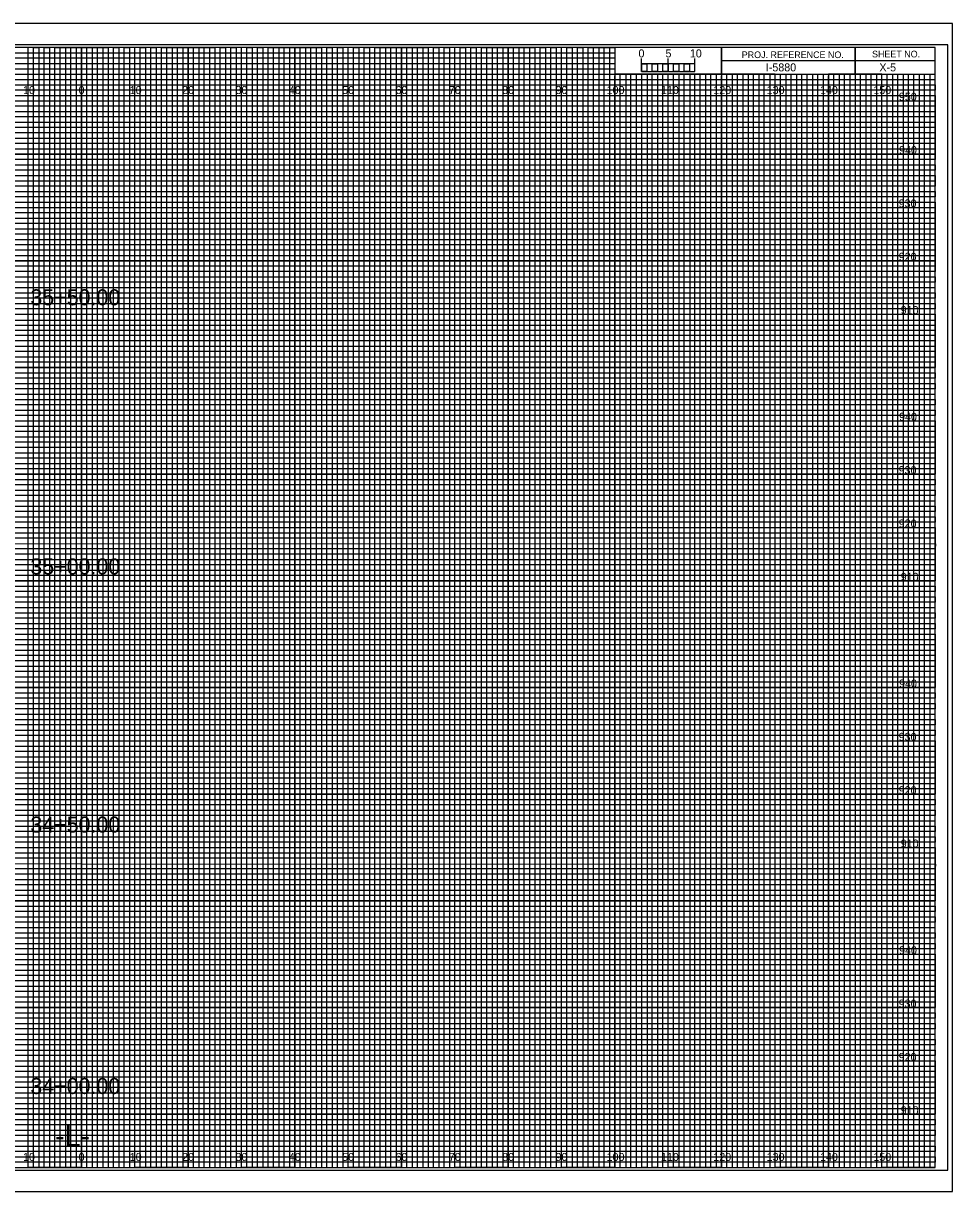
# Model space of a CAD drawing. Extents: x -13 to 323, y -4 to 3074.
# Drawn here: x 149.1 to 323.3, y 655.5 to 874.5 of the extents above; entities that cross this region are included whole.
import ezdxf

# ---------------------------------------------------------------- set-up
doc = ezdxf.new("R2010")
doc.units = 0
for name, color, linetype in [('Prop XS Alignment Label', 7, 'Continuous'), ('Prop XS Bar Scale Labels', 7, 'Continuous'), ('Prop XS Elevation Labels', 7, 'Continuous'), ('Prop XS Offset Labels', 7, 'Continuous'), ('Prop XS Project Number', 7, 'Continuous'), ('Prop XS Sheet Number', 7, 'Continuous'), ('Prop XS Station Labels', 7, 'Continuous'), ('Sheet Cross Section CELL', 7, 'Continuous'), ('Sheet Cross Section Grid Major CELL', 7, 'Continuous'), ('Sheet Cross Section Grid Middle CELL', 7, 'Continuous'), ('Sheet Cross Section Grid Minor 1 CELL', 7, 'Continuous'), ('Sheet Cross Section Grid Minor 2 CELL', 7, 'Continuous'), ('Sheet Cross Section Scale CELL', 7, 'Continuous'), ('Sheet Cutting Line CELL', 7, 'Continuous'), ('Sheet DOT Grid CELL', 7, 'Continuous'), ('Sheet Plot Border Inside CELL', 7, 'Continuous'), ('Sheet Plot Border Outside CELL', 7, 'Continuous')]:
    doc.layers.add(name, color=color, linetype=linetype)

msp = doc.modelspace()

# ---------------------------------------------------------------- linework, layer by layer
at = {"layer": 'Sheet Cross Section CELL'}
for p, q in [((305, 870), (305, 865)), ((305, 865), (305, 870)), ((280, 867.5), (280, 865)), ((320, 867.49), (280, 867.49)), ((280, 865), (320, 865))]:
    msp.add_line(p, q, dxfattribs=at)
for points in [[(320, 870), (0, 870), (0, 660), (320, 660)], [(280, 870), (260, 870), (260, 865.03), (280, 865.03)], [(320, 870), (280, 870), (280, 865), (320, 865)]]:
    msp.add_lwpolyline(points, close=True, dxfattribs=at)
at = {"layer": 'Sheet Cross Section Grid Major CELL'}
for p, q in [((150, 870), (140, 870)), ((150, 660), (150, 870)), ((170, 870), (160, 870)), ((160, 870), (160, 660)), ((170, 660), (170, 870)), ((190, 870), (180, 870)), ((180, 870), (180, 660)), ((190, 660), (190, 870)), ((210, 870), (200, 870)), ((200, 870), (200, 660)), ((210, 660), (210, 870)), ((230, 870), (220, 870)), ((220, 870), (220, 660)), ((230, 660), (230, 870)), ((250, 870), (240, 870)), ((240, 870), (240, 660)), ((250, 660), (250, 870)), ((260, 870), (260, 660)), ((270, 660), (270, 865)), ((290, 865), (280, 865)), ((280, 865), (280, 660)), ((290, 660), (290, 865)), ((310, 865), (300, 865)), ((300, 865), (300, 660)), ((310, 660), (310, 865)), ((160, 660), (150, 660)), ((180, 660), (170, 660)), ((200, 660), (190, 660)), ((220, 660), (210, 660)), ((240, 660), (230, 660)), ((260, 660), (250, 660)), ((280, 660), (270, 660)), ((300, 660), (290, 660)), ((320, 660), (310, 660)), ((320, 660), (320, 660))]:
    msp.add_line(p, q, dxfattribs=at)
for points in [[(0, 860), (320, 860), (320, 850), (0, 850)], [(0, 840), (320, 840), (320, 830), (0, 830)], [(0, 820), (320, 820), (320, 810), (0, 810)], [(0, 800), (320, 800), (320, 790), (0, 790)], [(0, 780), (320, 780), (320, 770), (0, 770)], [(0, 760), (320, 760), (320, 750), (0, 750)], [(0, 740), (320, 740), (320, 730), (0, 730)], [(0, 720), (320, 720), (320, 710), (0, 710)], [(0, 700), (320, 700), (320, 690), (0, 690)], [(0, 680), (320, 680), (320, 670), (0, 670)]]:
    msp.add_lwpolyline(points, dxfattribs=at)
at = {"layer": 'Sheet Cross Section Grid Middle CELL'}
for points in [[(145, 660), (155, 660), (155, 870), (165, 870), (165, 660), (175, 660), (175, 870), (185, 870), (185, 660), (195, 660), (195, 870), (205, 870), (205, 660), (215, 660), (215, 870), (225, 870), (225, 660), (235, 660), (235, 870), (245, 870), (245, 660), (255, 660), (255, 870), (259.93, 870), (260, 870), (260, 865), (264.99, 865), (264.99, 660), (275, 660), (275, 865), (285, 865), (285, 660), (295, 660), (295, 865), (305, 865), (305, 660), (315, 660), (315, 865)], [(0, 865), (275, 865)], [(0, 845), (320, 845), (320, 855), (0, 855)], [(0, 825), (320, 825), (320, 835), (0, 835)], [(0, 805), (320, 805), (320, 815), (0, 815)], [(0, 785), (320, 785), (320, 795), (0, 795)], [(0, 765), (320, 765), (320, 775), (0, 775)], [(0, 745), (320, 745), (320, 755), (0, 755)], [(0, 725), (320, 725), (320, 735), (0, 735)], [(0, 705), (320, 705), (320, 715), (0, 715)], [(0, 685), (320, 685), (320, 695), (0, 695)], [(0, 665), (320, 665), (320, 675), (0, 675)]]:
    msp.add_lwpolyline(points, dxfattribs=at)
at = {"layer": 'Sheet Cross Section Grid Minor 1 CELL'}
for p, q in [((0, 869), (260, 869)), ((260, 867.98), (0, 867.98)), ((260, 869), (260, 867.98)), ((0, 867), (260, 867)), ((260, 865.89), (0, 865.89)), ((260, 867), (260, 865.89)), ((0, 864), (320, 864))]:
    msp.add_line(p, q, dxfattribs=at)
for points in [[(0, 863), (270, 863), (320, 863), (320, 862), (0, 862)], [(0, 861), (320, 861), (320, 859), (0, 859)], [(0, 858), (320, 858), (320, 857), (0, 856.98)], [(0, 856), (320, 856), (320, 854), (0, 854)], [(0, 853), (320, 853), (320, 852), (0, 852)], [(0, 851), (320, 851), (320, 849), (0, 849)], [(0, 848), (320, 848), (320, 847), (0, 847)], [(0, 846), (320, 846), (320, 844), (0, 844)], [(0, 843), (320, 843), (320, 842), (0, 842)], [(0, 841), (320, 841), (320, 839), (0, 839)], [(0, 838), (320, 838), (320, 837), (0, 837)], [(0, 836), (320, 836), (320, 833.95), (320, 833), (320, 832), (0, 832)], [(0, 834), (320, 834), (320, 833), (0, 833)], [(0, 831), (320, 831), (320, 829), (0, 829.03)], [(0, 829.03), (320, 829), (320, 828), (0, 828)], [(0, 827), (320, 827), (320, 826), (0, 826)], [(0, 824), (320, 824), (320, 823), (0, 823)], [(0, 822), (320, 822), (320, 821), (0, 821)], [(-0.07, 818.89), (320, 818.89), (320, 817.88), (-0.07, 817.88)], [(0, 817), (320, 817), (320, 816), (0, 816)], [(0, 814), (320, 814), (320, 813), (0, 813)], [(0, 812), (320, 812), (320, 811), (0, 811)], [(0, 809), (320, 809), (320, 808), (0, 808)], [(0, 807), (320, 807), (320, 806), (0, 806)], [(0, 804), (320, 804), (320, 803), (0, 803)], [(0, 802), (320, 802), (320, 801), (0, 801)], [(0, 799), (320, 799), (319.99, 797.98), (0, 798)], [(0, 797), (320, 797), (320, 796), (0, 796)], [(0, 794), (320, 794), (320, 793), (0, 793)], [(0, 792), (320, 792), (320, 791), (0, 791)], [(0, 789), (320, 789), (320, 788), (0, 788)], [(0, 787), (320, 787), (320, 786), (0, 786)], [(0, 784), (320, 784), (320, 783), (0, 783)], [(0, 782), (320, 782), (320, 781), (0, 781)], [(0, 779), (320, 779), (320, 778), (0, 778)], [(0, 776.99), (320.07, 776.91), (320, 776), (0, 776)], [(0, 774), (320, 774), (320, 773), (0, 773)], [(0, 772), (320, 772), (320, 771), (0, 771)], [(0, 769), (320, 769), (320, 768), (0, 768)], [(0, 767), (320, 767), (320, 766), (0, 766)], [(0, 764), (320, 764), (320, 763), (0, 763)], [(0, 762), (320, 762), (320, 761), (0, 761)], [(0, 759), (320, 759), (320, 758), (0, 758)], [(0, 757), (320, 757), (320, 756), (0, 756)], [(0, 754), (320, 754), (320, 753), (0, 753)], [(0, 752), (320, 752), (320, 751), (0, 751)], [(0, 749), (320, 749), (320, 748), (0, 748)], [(0, 747), (320, 747), (320, 746), (0, 746)], [(0, 744), (320, 744), (320, 743), (0, 743)], [(0, 742), (320, 742), (320, 741), (0, 741)], [(0, 739), (320, 739), (319.99, 737.98), (0, 738)], [(0, 737), (320, 737), (320, 736), (0, 736)], [(0, 734), (320, 734), (320, 733), (0, 733)], [(0, 732), (320, 732), (320, 731), (0, 731)], [(0, 729), (320, 729), (320, 728), (0, 728)], [(0, 727), (320, 727), (320, 726), (0, 726)], [(0, 724), (320, 724), (320, 723), (0, 723)], [(0, 722), (320, 722), (320, 721), (0, 721)], [(0, 719), (320, 719), (320, 718), (0, 718)], [(0, 716.99), (320.07, 716.91), (320, 716), (0, 716)], [(0, 714), (320, 714), (320, 713), (0, 713)], [(0, 712), (320, 712), (320, 711), (0, 711)], [(0, 709), (320, 709), (320, 708), (0, 708)], [(0, 707), (320, 707), (320, 706), (0, 706)], [(0, 704), (320, 704), (320, 703), (0, 703)], [(0, 702), (320, 702), (320, 701), (0, 701)], [(0, 699), (320, 699), (320, 698), (0, 698)], [(0, 697), (320, 697), (320, 696), (0, 696)], [(0, 694), (320, 694), (320, 693), (0, 693)], [(0, 692), (320, 692), (320, 691), (0, 691)], [(0, 689), (320, 689), (320, 688), (0, 688)], [(0, 687), (320, 687), (320, 686), (0, 686)], [(0, 684), (320, 684), (320, 683), (0, 683)], [(0, 682), (320, 682), (320, 681), (0, 681)], [(0, 679), (320, 679), (320, 678), (0, 678)], [(0, 677), (320, 677), (320, 676), (0, 676)], [(0, 674), (320, 674), (320, 673), (0, 673)], [(0, 672), (320, 672), (320, 671), (0, 671)], [(0, 669), (320, 669), (320, 668), (0, 668)], [(0, 667), (320, 667), (320, 666), (0, 666)], [(0, 664), (320, 664), (320, 663), (0, 663)], [(0, 662), (320, 662), (320, 661), (0, 661)]]:
    msp.add_lwpolyline(points, dxfattribs=at)
at = {"layer": 'Sheet Cross Section Grid Minor 2 CELL'}
for p, q in [((267, 865), (266.01, 865)), ((266.01, 865), (266.01, 660)), ((267, 660), (267, 865)), ((269, 865), (268, 865)), ((268, 865), (268, 660)), ((269, 660), (269, 865)), ((266.01, 660), (265, 660)), ((268, 660), (267, 660))]:
    msp.add_line(p, q, dxfattribs=at)
for points in [[(150, 660), (151, 660), (151, 870), (152, 870), (152, 660)], [(152, 660), (153, 660), (153, 870), (154, 870), (154, 660)], [(155, 660), (156, 660), (156, 870), (157, 870), (157, 660)], [(157, 660), (158, 660), (158, 870), (159, 870), (159, 660)], [(160, 660), (161, 660), (161, 870), (162, 870), (162, 660)], [(162, 660), (163, 660), (163, 870), (164, 870), (164, 660)], [(165, 660), (166, 660), (166, 870), (167, 870), (167, 660)], [(167, 660), (168, 660), (168, 870), (169, 870), (169, 660)], [(170, 660), (171, 660), (171, 870), (172, 870), (172, 660)], [(172, 660), (173, 660), (173, 870), (174, 870), (174, 660)], [(175, 660), (176, 660), (176, 870), (177, 870), (177, 660)], [(177, 660), (178, 660), (178, 870), (179, 870), (179, 660)], [(180, 660), (181, 660), (181, 870), (182, 870), (182, 660)], [(182, 660), (183, 660), (183, 870), (184, 870), (184, 660)], [(185, 660), (186, 660), (186, 870), (187, 870), (187, 660)], [(187, 660), (188, 660), (188, 870), (189, 870), (189, 660)], [(190, 660), (191, 660), (191, 870), (192, 870), (192, 660)], [(192, 660), (193, 660), (193, 870), (194, 870), (194, 660)], [(195, 660), (196, 660), (196, 870), (197, 870), (197, 660)], [(197, 660), (198, 660), (198, 870), (199, 870), (199, 660)], [(200, 660), (201, 660), (201, 870), (202, 870), (202, 660)], [(202, 660), (203, 660), (203, 870), (204, 870), (204, 660)], [(205, 660), (206, 660), (206, 870), (207, 870), (207, 660)], [(207, 660), (208, 660), (208, 870), (209, 870), (209, 660)], [(210, 660), (211, 660), (211, 870), (212, 870), (212, 660)], [(212, 660), (213, 660), (213, 870), (214, 870), (214, 660)], [(215, 660), (216, 660), (216, 870), (217, 870), (217, 660)], [(217, 660), (218, 660), (218, 870), (219, 870), (219, 660)], [(220, 660), (221, 660), (221, 870), (222, 870), (222, 660)], [(222, 660), (223, 660), (223, 870), (224, 870), (224, 660)], [(225, 660), (226, 660), (226, 870), (227, 870), (227, 660)], [(227, 660), (228, 660), (228, 870), (229, 870), (229, 660)], [(230, 660), (231, 660), (231, 870), (232, 870), (232, 660)], [(232, 660), (233, 660), (233, 870), (234, 870), (234, 660)], [(235, 660), (236, 660), (236, 870), (237, 870), (237, 660)], [(237, 660), (238, 660), (238, 870), (239, 870), (239, 660)], [(240, 660), (241, 660), (241, 870), (242, 870), (242, 660)], [(242, 660), (243, 660), (243, 870), (244, 870), (244, 660)], [(245, 660), (246, 660), (246, 870), (247, 870), (247, 660)], [(247, 660), (248, 660), (248, 870), (249, 870), (249, 660)], [(250, 660), (251, 660), (251, 870), (252, 870), (252, 660)], [(252, 660), (253, 660), (253, 870), (254, 870), (254, 660)], [(255, 660), (256, 660), (256, 870), (257, 870), (257, 660)], [(257, 660), (258, 660), (258, 870), (259, 870), (259, 660)], [(260, 660), (261, 660), (261, 865), (262.02, 865), (262.02, 660)], [(262, 660), (263, 660), (263, 865), (263.99, 865), (263.99, 660)], [(270, 660), (270.98, 660), (270.98, 865), (272, 865), (272, 660)], [(272, 660), (273, 660), (273, 865), (274.05, 865), (274.05, 660)], [(275, 660), (276, 660), (276, 865), (277, 865), (277, 660)], [(277, 660), (278, 660), (278, 865), (279, 865), (279, 660)], [(280, 660), (281, 660), (281, 865), (282, 865), (282, 660)], [(282, 660), (283, 660), (283, 865), (284, 865), (284, 660)], [(285, 660), (286, 660), (286, 865), (287, 865), (287, 660)], [(287, 660), (288, 660), (288, 865), (289, 865), (289, 660)], [(290, 660), (291, 660), (291, 865), (292, 865), (292, 660)], [(292, 660), (293, 660), (293, 865), (294, 865), (294, 660)], [(295, 660), (296, 660), (296, 865), (297, 865), (297, 660)], [(297, 660), (298, 660), (298, 865), (299, 865), (299, 660)], [(300, 660), (301, 660), (301, 865), (302, 865), (302, 660)], [(302, 660), (303, 660), (303, 865), (304, 865), (304, 660)], [(305, 660), (306, 660), (306, 865), (307, 865), (307, 660)], [(307, 660), (308, 660), (308, 865), (309, 865), (309, 660)], [(310, 660), (311, 660), (311, 865), (312, 865), (312, 660)], [(312, 660), (313, 660), (313, 865), (314, 865), (314, 660)], [(315, 660), (316, 660), (316, 865), (317, 865), (317, 660)], [(317, 660), (318, 660), (318, 865), (319, 865), (319, 660)]]:
    msp.add_lwpolyline(points, dxfattribs=at)
at = {"layer": 'Sheet Cross Section Scale CELL'}
for p, q in [((265, 865.49), (265, 867.9)), ((265, 866.9), (265, 867.9)), ((270, 865.49), (270, 867.9)), ((275, 865.49), (275, 867.9)), ((275, 866.9), (275, 867.9))]:
    msp.add_line(p, q, dxfattribs=at)
for points in [[(275, 866.9), (265, 866.9), (265, 865.49), (275, 865.49)], [(265, 866.9), (266, 866.9), (266, 865.49), (265, 865.49)], [(267, 866.9), (268, 866.9), (268, 865.49), (267, 865.49)], [(269, 866.9), (270, 866.9), (270, 865.49), (269, 865.49)], [(271, 866.9), (272, 866.9), (272, 865.49), (271, 865.49)], [(273, 866.9), (274, 866.9), (274, 865.49), (273, 865.49)]]:
    msp.add_lwpolyline(points, close=True, dxfattribs=at)
at = {"layer": 'Sheet Cutting Line CELL'}
for p, q in [((323.3, 874.5), (-13.4, 874.5)), ((-13.4, 655.5), (323.3, 655.5))]:
    msp.add_line(p, q, dxfattribs=at)
at = {"layer": 'Sheet DOT Grid CELL'}
for p, q in [((150, 660), (150, 870)), ((160, 660), (160, 870)), ((170, 660), (170, 870)), ((180, 660), (180, 870)), ((190, 660), (190, 870)), ((200, 660), (200, 870)), ((210, 660), (210, 870)), ((220, 660), (220, 870)), ((230, 660), (230, 870)), ((240, 660), (240, 870)), ((250, 660), (250, 870)), ((260, 660), (260, 864.69)), ((270, 660), (270, 864.69)), ((280, 660), (280, 864.69)), ((290, 660), (290, 864.69)), ((300, 660), (300, 864.69)), ((310, 660), (310, 864.69)), ((0, 860), (320, 860)), ((0, 850), (320, 850)), ((0, 840), (320, 840)), ((0, 830), (320, 830)), ((0, 820), (320, 820)), ((0, 810), (320, 810)), ((0, 800), (320, 800)), ((0, 790), (320, 790)), ((0, 780), (320, 780)), ((0, 770), (320, 770)), ((0, 760), (320, 760)), ((0, 750), (320, 750)), ((0, 740), (320, 740)), ((0, 730), (320, 730)), ((0, 720), (320, 720)), ((0, 710), (320, 710)), ((0, 700), (320, 700)), ((0, 690), (320, 690)), ((0, 680), (320, 680)), ((0, 670), (320, 670))]:
    msp.add_line(p, q, dxfattribs=at)
at = {"layer": 'Sheet Plot Border Inside CELL'}
msp.add_lwpolyline([(-10.8, 659.5), (322.4, 659.5), (322.4, 870.5), (-10.8, 870.5)], close=True, dxfattribs=at)
at = {"layer": 'Sheet Plot Border Outside CELL'}
msp.add_lwpolyline([(-13.4, 655.5), (323.3, 655.5), (323.3, 874.5), (-13.4, 874.5)], close=True, dxfattribs=at)

# ---------------------------------------------------------------- texts
at = {"layer": 'Prop XS Alignment Label'}
msp.add_text('-L-', height=4, dxfattribs=at).set_placement((155.06, 664))
at = {"layer": 'Prop XS Bar Scale Labels'}
for s, p in [('5', (269.47, 868.12)), ('10', (274.04, 868.12))]:
    msp.add_text(s, height=1.5, dxfattribs=at).set_placement(p)
at = {"layer": 'Prop XS Elevation Labels'}
for s, p in [('950', (313.22, 860)), ('940', (313.26, 850)), ('930', (313.18, 840)), ('920', (313.19, 830)), ('910', (313.57, 820)), ('940', (313.26, 800)), ('930', (313.18, 790)), ('920', (313.19, 780)), ('910', (313.57, 770)), ('940', (313.26, 750)), ('930', (313.18, 740)), ('920', (313.19, 730)), ('910', (313.57, 720)), ('940', (313.26, 700)), ('930', (313.18, 690)), ('920', (313.19, 680)), ('910', (313.57, 670))]:
    msp.add_text(s, height=1.5, dxfattribs=at).set_placement(p)
at = {"layer": 'Prop XS Offset Labels'}
for s, p in [('10', (149.04, 861.25)), ('0', (159.45, 861.25)), ('0', (159.45, 861.25)), ('10', (169.04, 861.25)), ('20', (178.86, 861.25)), ('30', (188.86, 861.25)), ('40', (198.86, 861.25)), ('50', (208.86, 861.25)), ('60', (218.86, 861.25)), ('70', (228.86, 861.25)), ('80', (238.86, 861.25)), ('90', (248.86, 861.25)), ('100', (258.44, 861.25)), ('110', (268.62, 861.25)), ('120', (278.44, 861.25)), ('130', (288.44, 861.25)), ('140', (298.44, 861.25)), ('150', (308.44, 861.25)), ('10', (149.04, 661.25)), ('0', (159.45, 661.25)), ('0', (159.45, 661.25)), ('10', (169.04, 661.25)), ('20', (178.86, 661.25)), ('30', (188.86, 661.25)), ('40', (198.86, 661.25)), ('50', (208.86, 661.25)), ('60', (218.86, 661.25)), ('70', (228.86, 661.25)), ('80', (238.86, 661.25)), ('90', (248.86, 661.25)), ('100', (258.44, 661.25)), ('110', (268.62, 661.25)), ('120', (278.44, 661.25)), ('130', (288.44, 661.25)), ('140', (298.44, 661.25)), ('150', (308.44, 661.25))]:
    msp.add_text(s, height=1.5, dxfattribs=at).set_placement(p)
at = {"layer": 'Prop XS Project Number'}
msp.add_text('I-5880', height=1.5, dxfattribs=at).set_placement((288.28, 865.5))
at = {"layer": 'Prop XS Sheet Number'}
msp.add_text('X-5', height=1.5, dxfattribs=at).set_placement((309.57, 865.5))
at = {"layer": 'Prop XS Station Labels'}
for s, p in [('35+50.00', (150.41, 821.65)), ('35+00.00', (150.41, 771.2)), ('34+50.00', (150.41, 722.81)), ('34+00.00', (150.41, 673.8))]:
    msp.add_text(s, height=3, dxfattribs=at).set_placement(p)
at = {"layer": 'Sheet Cross Section CELL'}
for s, p in [('PROJ. REFERENCE NO.', (283.77, 867.99)), ('SHEET NO.', (308.19, 868.12))]:
    msp.add_text(s, height=1.25, dxfattribs=at).set_placement(p)
at = {"layer": 'Sheet Cross Section Scale CELL'}
msp.add_text('0', height=1.5, dxfattribs=at).set_placement((264.41, 868.12))

doc.saveas('drawing.dxf')
